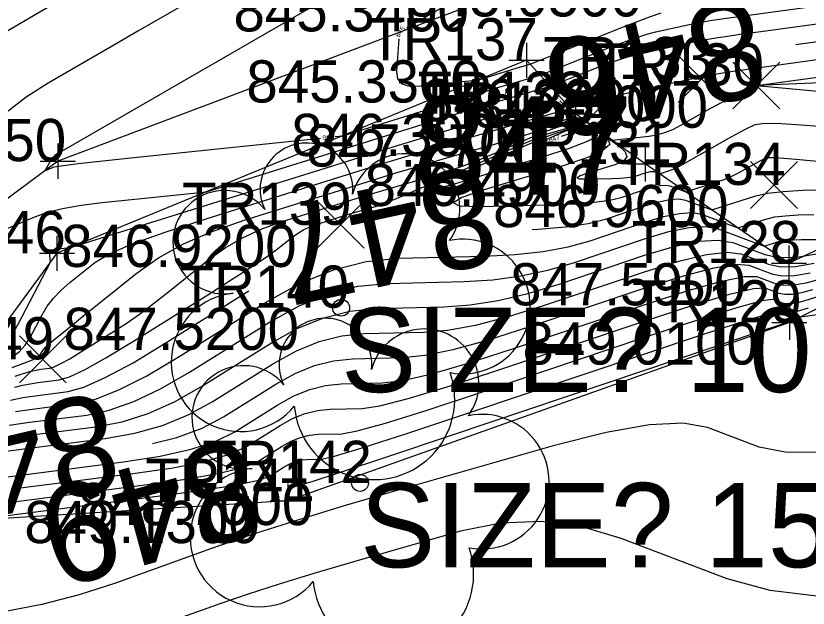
# Model space of a CAD drawing. Extents: x 1654928 to 1810050, y 486881 to 626330.
# Drawn here: x 1801379.97 to 1801402.5, y 489780.62 to 489797.47 of the extents above; entities that cross this region are included whole.
import ezdxf

# ---------------------------------------------------------------- set-up
doc = ezdxf.new("R2010")
doc.units = 0
for name, color, linetype in [('DR_X_Ditch', 7, 'Continuous'), ('DT_X_Contour_Major', 7, 'Continuous'), ('DT_X_Contour_Minor', 7, 'Continuous'), ('SV_X_Random_Point', 7, 'Continuous'), ('SV_X_Shot_Marker', 7, 'Continuous'), ('SV_X_Text_Elevation', 7, 'Continuous'), ('SV_X_Text_Name', 7, 'Continuous'), ('SV_X_Toe_of_Slope', 7, 'Continuous'), ('SV_X_Top_of_Bank', 7, 'Continuous'), ('VG_X_Cells', 7, 'Continuous'), ('VG_X_Text', 7, 'Continuous')]:
    doc.layers.add(name, color=color, linetype=linetype)

msp = doc.modelspace()

# ---------------------------------------------------------------- linework, layer by layer
at = {"layer": 'DR_X_Ditch'}
msp.add_lwpolyline([(1801415.613, 489805.461), (1801399.12, 489798.656), (1801394.115, 489798.231), (1801381.169, 489793.34), (1801378.227, 489791.154), (1801376.864, 489788.486), (1801373.817, 489786.687), (1801350.547, 489785.463), (1801345.905, 489787.547), (1801327.981, 489787.847), (1801322.506, 489787.279)], dxfattribs=at)
at = {"layer": 'DT_X_Contour_Major'}
for points in [[(1801411.674, 489809.49), (1801399.933, 489804.614), (1801397.704, 489803.688), (1801396.049, 489802.999), (1801394.968, 489802.548), (1801394.461, 489802.334), (1801393.874, 489802.081), (1801393.606, 489802.012), (1801393.24, 489801.995), (1801392.778, 489802.03), (1801392.218, 489802.116), (1801390.597, 489802.417), (1801390.015, 489802.487), (1801389.485, 489802.471), (1801389.009, 489802.37), (1801388.584, 489802.182), (1801386.273, 489800.844), (1801385.308, 489800.284), (1801384.116, 489799.592), (1801380.633, 489797.57), (1801379.484, 489796.895)], [(1801402.147, 489796.66), (1801405.642, 489797.139)], [(1801379.849, 489788.371), (1801380.037, 489788.706), (1801380.954, 489790.467), (1801380.939, 489790.666), (1801380.94, 489790.705), (1801380.95, 489790.737), (1801380.968, 489790.761), (1801380.996, 489790.778), (1801381.079, 489790.813), (1801381.114, 489790.825), (1801381.155, 489790.836), (1801381.203, 489790.845), (1801381.258, 489790.852), (1801381.528, 489790.88), (1801389.044, 489793.23), (1801390.513, 489793.687), (1801391.699, 489794.054), (1801392.601, 489794.329), (1801393.221, 489794.513), (1801393.995, 489794.737)], [(1801394.465, 489793.783), (1801395.168, 489794.075), (1801395.699, 489794.263), (1801396.057, 489794.347), (1801396.244, 489794.328), (1801396.512, 489794.139), (1801396.489, 489794.043), (1801396.219, 489793.896), (1801395.701, 489793.7), (1801394.935, 489793.453), (1801392.563, 489792.727), (1801391.883, 489792.532), (1801391.623, 489792.49), (1801391.783, 489792.603), (1801392.362, 489792.869), (1801394.465, 489793.783)], [(1801394.649, 489791.394), (1801394.815, 489791.401), (1801395.604, 489791.469), (1801396.246, 489791.566), (1801396.739, 489791.693), (1801397.856, 489792.069), (1801398.242, 489792.184), (1801398.564, 489792.25), (1801398.821, 489792.266), (1801399.013, 489792.231), (1801399.76, 489791.953), (1801401.014, 489792.351), (1801401.341, 489792.426), (1801401.785, 489792.48), (1801402.345, 489792.514), (1801403.021, 489792.526)], [(1801383.859, 489785.308), (1801384.548, 489785.483), (1801385.269, 489785.748), (1801385.88, 489786.068), (1801387.362, 489786.995), (1801387.916, 489787.301), (1801388.464, 489787.524), (1801389.008, 489787.662), (1801389.548, 489787.717), (1801390.979, 489787.752), (1801391.604, 489787.816), (1801392.405, 489787.981), (1801393.381, 489788.246), (1801394.533, 489788.613), (1801397.84, 489789.726), (1801398.956, 489790.08), (1801399.823, 489790.306), (1801400.441, 489790.406), (1801400.811, 489790.378), (1801401.465, 489790.134), (1801401.75, 489790.076), (1801402.113, 489790.084), (1801402.554, 489790.158)], [(1801387.82, 489784.124), (1801387.855, 489784.133), (1801387.917, 489784.139), (1801388.082, 489784.143), (1801388.394, 489784.231), (1801389.205, 489784.492), (1801390.517, 489784.926), (1801392.328, 489785.533), (1801397.825, 489787.383), (1801399.628, 489787.99), (1801400.918, 489788.424), (1801401.952, 489788.769), (1801401.958, 489788.767), (1801401.965, 489788.766), (1801401.969, 489788.767), (1801401.974, 489788.768), (1801401.989, 489788.773), (1801401.997, 489788.776), (1801402.051, 489788.803), (1801402.12, 489788.838), (1801402.144, 489788.85), (1801402.166, 489788.861), (1801402.185, 489788.87), (1801402.203, 489788.878), (1801402.277, 489788.91), (1801412.738, 489790.368)], [(1801379.825, 489786.544), (1801380.169, 489786.612), (1801380.52, 489786.665), (1801381.463, 489786.785), (1801381.903, 489786.907), (1801382.517, 489787.181), (1801383.304, 489787.607), (1801384.265, 489788.187), (1801386.601, 489789.649)]]:
    msp.add_lwpolyline(points, dxfattribs=at)
at = {"layer": 'DT_X_Contour_Minor'}
for points in [[(1801405.699, 489805.825), (1801400.036, 489803.473), (1801398.138, 489802.684), (1801396.69, 489802.081), (1801395.692, 489801.663), (1801395.145, 489801.431), (1801394.285, 489801.06), (1801393.95, 489800.948), (1801393.59, 489800.891), (1801393.204, 489800.888), (1801392.793, 489800.939), (1801391.663, 489801.149), (1801391.166, 489801.145), (1801390.522, 489800.975), (1801389.732, 489800.639), (1801388.795, 489800.137), (1801386.101, 489798.578), (1801385.131, 489798.017), (1801383.437, 489797.035), (1801382.712, 489796.615), (1801380.888, 489795.556), (1801380.263, 489795.159), (1801379.756, 489794.764)], [(1801403.233, 489802.455), (1801402.19, 489802.002), (1801399.548, 489800.904), (1801398.615, 489800.516), (1801397.798, 489800.173), (1801397.097, 489799.877), (1801396.512, 489799.626), (1801395.107, 489799.019), (1801394.639, 489798.821), (1801394.289, 489798.683), (1801394.057, 489798.604), (1801393.943, 489798.585), (1801393.795, 489798.612), (1801393.694, 489798.59), (1801393.502, 489798.506), (1801393.218, 489798.357), (1801392.843, 489798.145), (1801391.078, 489797.124)], [(1801389.005, 489798.092), (1801381.143, 489793.542), (1801381.085, 489793.502), (1801381.034, 489793.457), (1801380.99, 489793.406), (1801380.954, 489793.349), (1801380.801, 489793.067), (1801381.058, 489793.175), (1801381.258, 489793.211), (1801381.748, 489793.272), (1801382.528, 489793.36), (1801383.598, 489793.473), (1801388.637, 489793.995)], [(1801389.055, 489794.039), (1801389.267, 489794.061), (1801392.888, 489795.192), (1801393.73, 489795.451), (1801393.979, 489795.525), (1801394.878, 489795.784), (1801396.85, 489796.572), (1801397.25, 489796.727), (1801397.603, 489796.852), (1801397.91, 489796.949), (1801398.172, 489797.017), (1801399.027, 489797.208), (1801399.357, 489797.277), (1801399.467, 489797.297), (1801399.713, 489797.337), (1801400.172, 489797.403), (1801402.896, 489797.778)], [(1801390.865, 489796.82), (1801390.796, 489795.886), (1801390.825, 489795.68), (1801390.948, 489795.544), (1801391.164, 489795.476), (1801391.474, 489795.479), (1801393.137, 489795.651), (1801393.922, 489795.897), (1801394.076, 489795.944), (1801394.2, 489795.983), (1801394.294, 489796.011), (1801394.359, 489796.031), (1801394.592, 489796.098), (1801397.127, 489797.111), (1801397.621, 489797.305), (1801398.018, 489797.453), (1801398.316, 489797.556)], [(1801379.542, 489791.352), (1801380.464, 489791.74), (1801380.846, 489791.875), (1801381.3, 489791.991), (1801381.828, 489792.086), (1801382.428, 489792.162), (1801385.398, 489792.47), (1801390.67, 489794.119), (1801391.7, 489794.44), (1801392.532, 489794.697), (1801393.165, 489794.89), (1801393.6, 489795.019), (1801395.165, 489795.471), (1801396.573, 489796.034), (1801396.878, 489796.148), (1801397.189, 489796.251), (1801397.505, 489796.342), (1801397.827, 489796.421), (1801398.693, 489796.615), (1801398.993, 489796.682), (1801399.243, 489796.735), (1801399.443, 489796.775), (1801399.593, 489796.802), (1801399.928, 489796.857), (1801400.147, 489796.89), (1801400.554, 489796.948), (1801401.149, 489797.031), (1801404.269, 489797.459)], [(1801412.46, 489795.962), (1801401.026, 489795.492), (1801408.388, 489796.501)], [(1801379.866, 489787.775), (1801380.07, 489787.919), (1801380.242, 489788.103), (1801380.384, 489788.326), (1801380.721, 489788.972), (1801380.865, 489789.211), (1801381.044, 489789.443), (1801381.258, 489789.667), (1801381.508, 489789.885), (1801382.22, 489790.455), (1801382.62, 489790.694), (1801383.284, 489790.983), (1801384.214, 489791.322), (1801385.408, 489791.712), (1801388.946, 489792.819), (1801390.185, 489793.204), (1801391.247, 489793.531), (1801392.133, 489793.798), (1801392.842, 489794.007), (1801395.738, 489794.844), (1801396.02, 489794.956), (1801396.135, 489794.991), (1801396.359, 489795.048), (1801396.693, 489795.127), (1801397.137, 489795.228), (1801398.465, 489795.527), (1801398.925, 489795.628), (1801399.308, 489795.71), (1801399.615, 489795.772), (1801399.846, 489795.813), (1801400.359, 489795.897), (1801400.695, 489795.948), (1801401.319, 489796.037), (1801403.431, 489796.329)], [(1801379.864, 489787.47), (1801380.198, 489787.59), (1801380.443, 489787.689), (1801380.6, 489787.768), (1801380.669, 489787.827), (1801380.737, 489787.956), (1801380.829, 489788.055), (1801381.057, 489788.255), (1801381.419, 489788.555), (1801381.915, 489788.956), (1801383.419, 489790.16), (1801384.032, 489790.592), (1801384.744, 489790.987), (1801385.554, 489791.343), (1801386.464, 489791.662), (1801389.019, 489792.461), (1801389.93, 489792.744), (1801390.747, 489792.994), (1801391.469, 489793.211), (1801392.096, 489793.395), (1801393.644, 489793.843), (1801394.173, 489793.998), (1801394.597, 489794.13), (1801394.918, 489794.238), (1801395.135, 489794.321), (1801395.575, 489794.513), (1801395.738, 489794.562), (1801395.899, 489794.566), (1801396.056, 489794.526), (1801396.211, 489794.441), (1801396.925, 489793.938), (1801397.971, 489794.05), (1801398.196, 489794.087), (1801398.422, 489794.152), (1801398.649, 489794.243), (1801398.878, 489794.361), (1801399.49, 489794.711), (1801399.711, 489794.835), (1801399.914, 489794.946), (1801400.101, 489795.044), (1801400.272, 489795.129), (1801401.026, 489795.492), (1801407.291, 489794.915)], [(1801379.943, 489786.912), (1801380.158, 489786.965), (1801380.377, 489787.009), (1801380.6, 489787.042), (1801381.2, 489787.119), (1801381.498, 489787.207), (1801381.943, 489787.415), (1801382.533, 489787.743), (1801383.269, 489788.189), (1801385.427, 489789.54), (1801386.156, 489789.999), (1801386.723, 489790.365), (1801387.128, 489790.636), (1801387.372, 489790.814), (1801387.806, 489791.162), (1801387.976, 489791.284), (1801388.161, 489791.392), (1801388.361, 489791.484), (1801388.574, 489791.561), (1801389.164, 489791.745), (1801389.563, 489791.868), (1801389.73, 489791.918), (1801389.874, 489791.961), (1801390.232, 489792.064), (1801390.452, 489792.143), (1801390.845, 489792.301), (1801391.41, 489792.54), (1801392.149, 489792.858), (1801394.348, 489793.815), (1801395.091, 489794.113), (1801395.672, 489794.291), (1801396.091, 489794.348), (1801396.347, 489794.285), (1801396.814, 489793.956), (1801396.864, 489793.816), (1801396.661, 489793.644), (1801396.208, 489793.439), (1801395.502, 489793.201), (1801393.286, 489792.523), (1801392.653, 489792.302), (1801392.417, 489792.15), (1801392.579, 489792.067), (1801393.137, 489792.051), (1801395.156, 489792.1), (1801395.851, 489792.127), (1801396.419, 489792.171), (1801396.862, 489792.231), (1801397.18, 489792.309), (1801397.859, 489792.537), (1801398.094, 489792.608), (1801398.289, 489792.648), (1801398.445, 489792.657), (1801398.562, 489792.636), (1801399.016, 489792.467), (1801399.9, 489792.747), (1801400.08, 489792.808), (1801400.243, 489792.871), (1801400.389, 489792.937), (1801400.517, 489793.004), (1801400.836, 489793.186), (1801400.946, 489793.249), (1801401.111, 489793.339), (1801401.167, 489793.367), (1801401.29, 489793.427), (1801401.378, 489793.442), (1801401.551, 489793.442), (1801401.808, 489793.429), (1801402.149, 489793.401), (1801403.172, 489793.306)], [(1801379.951, 489787.22), (1801380.07, 489787.259), (1801380.309, 489787.337), (1801380.399, 489787.364), (1801380.491, 489787.386), (1801380.585, 489787.405), (1801380.681, 489787.419), (1801380.938, 489787.452), (1801381.065, 489787.49), (1801381.256, 489787.579), (1801381.509, 489787.72), (1801381.824, 489787.911), (1801382.749, 489788.49), (1801383.107, 489788.723), (1801383.487, 489788.989), (1801383.888, 489789.288), (1801384.312, 489789.62), (1801385.471, 489790.547), (1801385.924, 489790.874), (1801386.417, 489791.161), (1801386.949, 489791.406), (1801387.519, 489791.611), (1801389.652, 489792.277), (1801390.155, 489792.431), (1801390.599, 489792.565), (1801390.985, 489792.678), (1801391.938, 489792.953), (1801392.312, 489793.07), (1801392.721, 489793.216), (1801393.164, 489793.389), (1801393.642, 489793.59), (1801394.961, 489794.164), (1801395.425, 489794.33), (1801395.828, 489794.398), (1801396.17, 489794.369), (1801396.45, 489794.242), (1801397.116, 489793.773), (1801397.298, 489793.608), (1801397.343, 489793.464), (1801397.252, 489793.342), (1801397.026, 489793.241), (1801396.239, 489793), (1801396.015, 489792.922), (1801395.931, 489792.868), (1801395.988, 489792.839), (1801396.186, 489792.833), (1801396.903, 489792.851), (1801397.149, 489792.86), (1801397.351, 489792.876), (1801397.508, 489792.897), (1801397.621, 489792.925), (1801397.862, 489793.006), (1801397.945, 489793.031), (1801398.014, 489793.045), (1801398.07, 489793.048), (1801398.111, 489793.041), (1801398.272, 489792.981), (1801398.586, 489793.08), (1801398.678, 489793.118), (1801398.821, 489793.189), (1801399.014, 489793.293), (1801399.258, 489793.43), (1801399.974, 489793.84), (1801400.222, 489793.981), (1801400.429, 489794.096), (1801400.595, 489794.185), (1801400.719, 489794.248), (1801400.996, 489794.381), (1801401.195, 489794.415), (1801401.583, 489794.417), (1801402.162, 489794.386), (1801402.93, 489794.323)], [(1801395.68, 489794.229), (1801395.862, 489794.305), (1801396, 489794.354), (1801396.093, 489794.375), (1801396.141, 489794.371), (1801396.211, 489794.322), (1801396.205, 489794.297), (1801396.134, 489794.259), (1801396, 489794.208), (1801395.802, 489794.144), (1801395.479, 489794.045)], [(1801395.077, 489793.924), (1801395.011, 489793.905), (1801394.943, 489793.894), (1801394.984, 489793.923), (1801395.135, 489793.992), (1801395.68, 489794.229)], [(1801379.966, 489786.217), (1801380.439, 489786.288), (1801381.725, 489786.452), (1801382.266, 489786.58), (1801382.923, 489786.841), (1801383.697, 489787.236), (1801384.588, 489787.763), (1801387.119, 489789.347), (1801388.064, 489789.869), (1801389.001, 489790.249), (1801389.931, 489790.486), (1801390.852, 489790.58), (1801393.297, 489790.639), (1801394.173, 489790.684), (1801394.965, 489790.771), (1801395.673, 489790.902), (1801396.298, 489791.077), (1801397.852, 489791.6), (1801398.39, 489791.761), (1801398.838, 489791.853), (1801399.196, 489791.875), (1801399.464, 489791.827), (1801400.503, 489791.439), (1801401.333, 489791.702), (1801401.549, 489791.752), (1801401.842, 489791.788), (1801402.212, 489791.81), (1801402.659, 489791.818)], [(1801379.779, 489785.828), (1801380.359, 489785.91), (1801381.988, 489786.118), (1801382.629, 489786.253), (1801383.33, 489786.502), (1801384.09, 489786.864), (1801384.911, 489787.339), (1801387.18, 489788.759), (1801388.027, 489789.227), (1801388.867, 489789.568), (1801389.7, 489789.78), (1801390.526, 489789.864), (1801392.718, 489789.918), (1801393.531, 489789.967), (1801394.325, 489790.074), (1801395.1, 489790.238), (1801395.857, 489790.461), (1801397.849, 489791.132), (1801398.539, 489791.338), (1801399.113, 489791.456), (1801399.572, 489791.484), (1801399.915, 489791.422), (1801401.247, 489790.926), (1801401.651, 489791.054), (1801401.756, 489791.078), (1801401.899, 489791.095), (1801402.079, 489791.106), (1801402.297, 489791.11), (1801403.401, 489791.114)], [(1801379.593, 489785.438), (1801380.279, 489785.533), (1801382.25, 489785.785), (1801382.992, 489785.926), (1801383.736, 489786.162), (1801384.483, 489786.492), (1801385.234, 489786.915), (1801387.241, 489788.171), (1801387.99, 489788.585), (1801388.733, 489788.886), (1801389.469, 489789.074), (1801390.2, 489789.148), (1801392.138, 489789.196), (1801392.888, 489789.25), (1801393.685, 489789.376), (1801394.527, 489789.574), (1801395.416, 489789.845), (1801397.846, 489790.663), (1801398.687, 489790.916), (1801399.385, 489791.059), (1801399.941, 489791.095), (1801400.354, 489791.021), (1801401.268, 489790.681), (1801401.665, 489790.6), (1801402.172, 489790.611), (1801402.788, 489790.715)], [(1801379.407, 489785.049), (1801380.198, 489785.156), (1801382.513, 489785.451), (1801383.354, 489785.6), (1801384.142, 489785.822), (1801384.876, 489786.12), (1801385.557, 489786.492), (1801387.301, 489787.583), (1801387.953, 489787.943), (1801388.599, 489788.205), (1801389.239, 489788.368), (1801389.874, 489788.433), (1801391.559, 489788.474), (1801392.246, 489788.533), (1801393.045, 489788.678), (1801393.954, 489788.91), (1801394.974, 489789.229), (1801397.843, 489790.195), (1801398.821, 489790.498), (1801399.604, 489790.683), (1801400.191, 489790.75), (1801400.583, 489790.7), (1801401.367, 489790.408), (1801401.708, 489790.338), (1801402.142, 489790.347), (1801402.671, 489790.436)], [(1801379.035, 489784.27), (1801380.037, 489784.401), (1801383.038, 489784.784), (1801384.08, 489784.946), (1801384.955, 489785.143), (1801385.663, 489785.376), (1801386.203, 489785.644), (1801387.423, 489786.407), (1801387.878, 489786.659), (1801388.33, 489786.842), (1801388.778, 489786.956), (1801389.222, 489787.002), (1801390.4, 489787.03), (1801390.962, 489787.099), (1801391.765, 489787.283), (1801392.808, 489787.582), (1801394.092, 489787.997), (1801397.837, 489789.257), (1801399.09, 489789.662), (1801400.042, 489789.93), (1801400.691, 489790.061), (1801401.039, 489790.056), (1801401.564, 489789.861), (1801401.792, 489789.814), (1801402.083, 489789.82), (1801402.437, 489789.88), (1801402.854, 489789.993)], [(1801379.957, 489784.024), (1801383.301, 489784.451), (1801384.443, 489784.619), (1801385.361, 489784.803), (1801386.056, 489785.004), (1801386.526, 489785.22), (1801387.484, 489785.82), (1801387.841, 489786.017), (1801388.196, 489786.161), (1801388.547, 489786.25), (1801388.895, 489786.286), (1801389.821, 489786.308), (1801390.32, 489786.382), (1801391.125, 489786.585), (1801392.235, 489786.918), (1801393.651, 489787.381), (1801397.834, 489788.789), (1801399.225, 489789.244), (1801400.261, 489789.553), (1801400.941, 489789.717), (1801401.267, 489789.734), (1801401.662, 489789.587), (1801401.834, 489789.552), (1801402.054, 489789.557), (1801402.32, 489789.602), (1801402.634, 489789.687)], [(1801378.662, 489783.491), (1801383.563, 489784.118), (1801384.805, 489784.292), (1801385.767, 489784.464), (1801386.449, 489784.632), (1801386.849, 489784.797), (1801387.544, 489785.232), (1801387.804, 489785.375), (1801388.061, 489785.479), (1801388.317, 489785.544), (1801388.569, 489785.57), (1801389.241, 489785.587), (1801389.678, 489785.665), (1801390.485, 489785.887), (1801391.663, 489786.254), (1801393.21, 489786.765), (1801397.831, 489788.32), (1801399.359, 489788.826), (1801400.48, 489789.177), (1801401.192, 489789.372), (1801401.495, 489789.413), (1801401.761, 489789.314), (1801401.877, 489789.29), (1801402.024, 489789.293), (1801402.203, 489789.323), (1801402.414, 489789.38), (1801403.019, 489789.569)], [(1801378.541, 489783.109), (1801384.356, 489783.852), (1801385.466, 489784.004), (1801386.306, 489784.141), (1801386.875, 489784.264), (1801387.172, 489784.373), (1801387.605, 489784.644), (1801387.767, 489784.733), (1801387.927, 489784.798), (1801388.086, 489784.839), (1801388.243, 489784.855), (1801388.662, 489784.865), (1801389.036, 489784.948), (1801389.845, 489785.19), (1801391.09, 489785.59), (1801392.769, 489786.149), (1801397.828, 489787.852), (1801399.494, 489788.408), (1801400.699, 489788.8), (1801401.442, 489789.028), (1801401.724, 489789.091), (1801401.86, 489789.04), (1801401.919, 489789.028), (1801401.994, 489789.03), (1801402.086, 489789.045), (1801402.194, 489789.074), (1801402.504, 489789.171)], [(1801402.985, 489785.047), (1801401.848, 489785.058), (1801401.101, 489785.201), (1801399.632, 489785.759), (1801398.945, 489785.884), (1801397.985, 489785.839), (1801396.752, 489785.624), (1801395.247, 489785.24), (1801390.868, 489783.99), (1801389.304, 489783.533), (1801387.894, 489783.102), (1801386.639, 489782.697), (1801385.538, 489782.316), (1801382.809, 489781.336), (1801381.774, 489781), (1801380.714, 489780.726), (1801379.629, 489780.515)], [(1801402.819, 489780.959), (1801401.416, 489781.121), (1801400.194, 489781.462), (1801397.179, 489782.608), (1801396.045, 489782.943), (1801394.907, 489783.088), (1801393.763, 489783.043), (1801392.614, 489782.809), (1801389.542, 489781.932), (1801388.445, 489781.612), (1801387.456, 489781.31), (1801386.575, 489781.025), (1801385.803, 489780.758), (1801383.889, 489780.071)]]:
    msp.add_lwpolyline(points, dxfattribs=at)
at = {"layer": 'SV_X_Random_Point'}
for p, q in [((1801398.803, 489795.007), (1801400.136, 489796.342)), ((1801398.803, 489796.342), (1801400.136, 489795.007)), ((1801400.359, 489794.824), (1801401.692, 489796.159)), ((1801400.359, 489796.159), (1801401.692, 489794.824)), ((1801395.438, 489793.718), (1801396.772, 489795.053)), ((1801395.438, 489795.053), (1801396.772, 489793.718)), ((1801400.858, 489791.995), (1801402.191, 489793.33)), ((1801400.858, 489793.33), (1801402.191, 489791.995)), ((1801388.541, 489790.863), (1801389.874, 489792.198)), ((1801388.541, 489792.198), (1801389.874, 489790.863)), ((1801380.074, 489787.035), (1801381.407, 489788.37)), ((1801380.074, 489788.37), (1801381.407, 489787.035))]:
    msp.add_line(p, q, dxfattribs=at)
at = {"layer": 'SV_X_Shot_Marker'}
for p, q in [((1801394.491, 489796.708), (1801394.491, 489795.708)), ((1801393.991, 489796.208), (1801394.991, 489796.208)), ((1801394.491, 489796.208), (1801394.491, 489796.208)), ((1801395.881, 489795.187), (1801395.881, 489794.187)), ((1801395.381, 489794.687), (1801396.381, 489794.687)), ((1801395.881, 489794.687), (1801395.881, 489794.687)), ((1801381.169, 489793.84), (1801381.169, 489792.84)), ((1801397.863, 489793.763), (1801397.863, 489792.763)), ((1801380.669, 489793.34), (1801381.669, 489793.34)), ((1801381.169, 489793.34), (1801381.169, 489793.34)), ((1801397.363, 489793.263), (1801398.363, 489793.263)), ((1801397.863, 489793.263), (1801397.863, 489793.263)), ((1801381.141, 489791.22), (1801381.141, 489790.22)), ((1801401.953, 489790.938), (1801401.953, 489789.938)), ((1801380.641, 489790.72), (1801381.641, 489790.72)), ((1801381.141, 489790.72), (1801381.141, 489790.72)), ((1801401.453, 489790.438), (1801402.453, 489790.438)), ((1801401.953, 489790.438), (1801401.953, 489790.438)), ((1801401.963, 489789.253), (1801401.963, 489788.253)), ((1801401.463, 489788.753), (1801402.463, 489788.753)), ((1801401.963, 489788.753), (1801401.963, 489788.753)), ((1801387.705, 489784.174), (1801387.705, 489783.174)), ((1801387.205, 489783.674), (1801388.205, 489783.674)), ((1801387.705, 489783.674), (1801387.705, 489783.674))]:
    msp.add_line(p, q, dxfattribs=at)
at = {"layer": 'SV_X_Toe_of_Slope'}
msp.add_lwpolyline([(1801417.791, 489799.995), (1801412.832, 489796.754), (1801412.089, 489795.17), (1801401.953, 489790.438), (1801397.863, 489793.263), (1801395.881, 489794.687), (1801394.491, 489796.208), (1801381.141, 489790.72), (1801379.18, 489788.057), (1801375.237, 489785.681), (1801360.556, 489782.746), (1801350.439, 489783.352), (1801348.143, 489785.528), (1801335.479, 489785.306), (1801328.907, 489786.007), (1801321.924, 489784.909)], dxfattribs=at)
at = {"layer": 'SV_X_Top_of_Bank'}
msp.add_lwpolyline([(1801414.708, 489795.331), (1801414.041, 489794.432), (1801412.967, 489794.649), (1801413.875, 489794.726), (1801401.963, 489788.753), (1801387.705, 489783.674), (1801376.875, 489783.007), (1801368.983, 489780.458), (1801361.095, 489781.125), (1801348.111, 489781.288), (1801336.05, 489778.687), (1801318.855, 489781.567)], dxfattribs=at)
at = {"layer": 'VG_X_Cells'}
for centre in [(1801389.219, 489789.17), (1801389.758, 489784.186)]:
    msp.add_circle(centre, 0.24, dxfattribs=at)
for centre, radius, start, end in [((1801388.235, 489792.538), 1.317, 354.0047, 205.9741), ((1801391.045, 489791.999), 1.553, 323.83, 165.0376), ((1801385.909, 489791.034), 1.471, 39.0625, 279.5412), ((1801392.679, 489789.206), 1.915, 259.1453, 101.4596), ((1801386.365, 489787.622), 1.974, 96.1722, 320.5737), ((1801388.774, 489787.553), 1.317, 354.0047, 205.9741), ((1801391.584, 489787.015), 1.553, 323.83, 165.0376), ((1801386.449, 489786.05), 1.471, 39.0625, 279.5412), ((1801390.165, 489786.565), 2.284, 184.9476, 19.4572), ((1801393.218, 489784.222), 1.915, 259.1453, 101.4596), ((1801386.905, 489782.637), 1.974, 96.1722, 320.5737), ((1801390.704, 489781.581), 2.284, 184.9476, 19.4572)]:
    msp.add_arc(centre, radius, start, end, dxfattribs=at)

# ---------------------------------------------------------------- texts
at = {"layer": 'DT_X_Contour_Major'}
for s, rotation, p in [('846', 193.2749, (1801400.887, 489798.06)), ('847', 192.233, (1801393.282, 489793.267)), ('848', 193.222, (1801382.503, 489786.82)), ('849', 195.2843, (1801386.453, 489785.516))]:
    msp.add_text(s, height=2.8, rotation=rotation, dxfattribs=at).set_placement(p)
msp.add_text('847', height=2.8, dxfattribs=at).set_placement((1801391.269, 489792.383))
at = {"layer": 'DT_X_Contour_Minor'}
for s, rotation, p in [('845', 54.9311, (1801390.862, 489796.848)), ('846', 185.9175, (1801389.002, 489794.103)), ('847', 16.7433, (1801395.145, 489793.87))]:
    msp.add_text(s, height=0.14, rotation=rotation, dxfattribs=at).set_placement(p)
at = {"layer": 'SV_X_Text_Elevation'}
for s, p in [('845.0500', (1801391.08, 489797.456)), ('845.3400', (1801386.16, 489797.031)), ('845.3300', (1801386.527, 489795.008)), ('846.2300', (1801391.524, 489794.475)), ('846.4000', (1801392.957, 489794.292)), ('846.3000', (1801387.803, 489793.487)), ('847.2700', (1801388.235, 489793.185)), ('846.4900', (1801389.889, 489792.063)), ('846.9600', (1801393.541, 489791.463)), ('846.9200', (1801381.262, 489790.33)), ('847.5900', (1801394.026, 489789.238)), ('847.5200', (1801381.33, 489787.97)), ('849.0100', (1801394.377, 489787.553)), ('848.7000', (1801381.737, 489782.986)), ('849.1300', (1801380.214, 489782.474))]:
    msp.add_text(s, height=1.2, dxfattribs=at).set_placement(p)
at = {"layer": 'SV_X_Text_Name'}
for s, p in [('TR137', (1801389.995, 489796.208)), ('TR133', (1801394.973, 489795.674)), ('TR130', (1801396.425, 489795.492)), ('TR132', (1801391.394, 489794.687)), ('TR138', (1801391.599, 489794.385)), ('TR150', (1801376.587, 489793.34)), ('TR131', (1801393.801, 489793.263)), ('TR134', (1801397.038, 489792.663)), ('TR139', (1801384.702, 489791.53)), ('TR146', (1801376.578, 489790.72)), ('TR128', (1801397.485, 489790.438)), ('TR140', (1801384.628, 489789.17)), ('TR129', (1801397.495, 489788.753)), ('TR149', (1801376.244, 489787.702)), ('TR142', (1801385.28, 489784.186)), ('TR141', (1801383.652, 489783.674))]:
    msp.add_text(s, height=1.2, dxfattribs=at).set_placement(p)
at = {"layer": 'VG_X_Text'}
for s, p in [('SIZE? 10" KIND?', (1801389.219, 489786.77)), ('SIZE? 15" KIND?', (1801389.758, 489781.786))]:
    msp.add_text(s, height=2.4, dxfattribs=at).set_placement(p)

doc.saveas('drawing.dxf')
